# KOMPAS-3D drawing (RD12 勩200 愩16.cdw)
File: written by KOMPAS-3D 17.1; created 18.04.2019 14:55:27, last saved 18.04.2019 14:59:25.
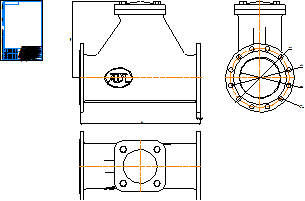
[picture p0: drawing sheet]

Sheet 1: A4, portrait

Title block, sheet 1: name: RD12 Ду200 Ру16; material: Внимание! Данный продукт является объектом авторского права ООО «Торговый Дом АДЛ». / Запрещается изменение, копирование, распространение / (в том числе путем копирования на другие сайты и ресурсы в Интернете) / или любое иное использование информации и объектов без предварительного / согласия правообладателя (ООО «Торговый Дом АДЛ»).; mass: 246,34; sheets: 1; organisation: ООО "Торговый дом АДЛ"; sheet format: A4; stored path: \\adlc.lan\data\АДЛ_ПКД\3D-модели\ADL production\Клапаны обратные ГРАНЛОК\RD12\KOMPAS 2D\RD12 Ду200 Ру16.cdw

Views: Вид 1, Проекционный вид 2, Проекционный вид 3
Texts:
  user
Dimensions and other numbers on the sheet: 17; 3; 594; 380; 295; 340; 200; 23; 12 отв.; 1:1; 1; 246,34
